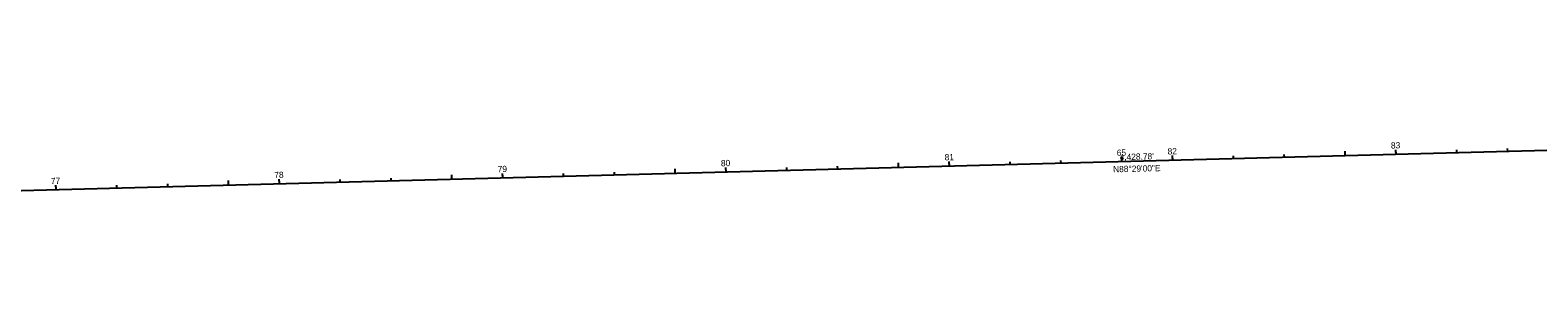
# Model space of a CAD drawing. Extents: x 2402033 to 2407434, y 498266 to 500417.
# Drawn here: x 2404722 to 2405397, y 498666 to 498783 of the extents above; entities that cross this region are included whole.
import ezdxf

# ---------------------------------------------------------------- set-up
doc = ezdxf.new("R2010")
doc.units = 0
for name, color, linetype in [('BR_P_Rail_Object', 7, 'Continuous'), ('DR_P_Inlet_Protection', 7, 'Continuous'), ('DR_X_Cells', 7, 'Continuous'), ('DR_X_Elev_Flow', 7, 'Continuous'), ('PV_P_EOP', 7, 'Continuous'), ('PV_P_Shoulder', 7, 'Continuous'), ('RD_P_GR_Lt', 7, 'Continuous'), ('SN_X_Public', 7, 'Continuous'), ('UT_X_Gas_Cells', 7, 'Continuous'), ('UT_X_Telecom_Cells', 7, 'Continuous')]:
    doc.layers.add(name, color=color, linetype=linetype)

msp = doc.modelspace()

# ---------------------------------------------------------------- linework, layer by layer
at = {"layer": 'PV_P_EOP'}
msp.add_line((2403004.47, 498665.82), (2407431.7, 498783.04), dxfattribs=at)
at = {"layer": 'PV_P_Shoulder'}
for p, q in [((2405210.95, 498724.24), (2405210.89, 498726.24)), ((2405233.69, 498724.84), (2405233.66, 498726.04)), ((2405310.91, 498726.89), (2405310.88, 498728.08)), ((2405333.66, 498727.49), (2405333.63, 498728.69)), ((2404911.05, 498716.3), (2404911.02, 498717.5)), ((2404933.8, 498716.9), (2404933.77, 498718.1)), ((2405011.02, 498718.95), (2405010.99, 498720.14)), ((2405033.76, 498719.55), (2405033.71, 498721.55)), ((2405110.98, 498721.59), (2405110.95, 498722.79)), ((2405133.73, 498722.19), (2405133.7, 498723.39)), ((2404733.87, 498711.61), (2404733.84, 498712.81)), ((2404811.09, 498713.65), (2404811.06, 498714.85)), ((2404833.83, 498714.25), (2404833.8, 498715.45))]:
    msp.add_line(p, q, dxfattribs=at)
at = {"layer": 'RD_P_GR_Lt'}
for p, q in [((2405133.73, 498722.19), (2405133.67, 498724.19)), ((2405160.96, 498722.92), (2405160.93, 498724.11)), ((2405183.71, 498723.52), (2405183.68, 498724.72)), ((2405210.95, 498724.24), (2405210.89, 498726.24)), ((2405233.69, 498724.84), (2405233.64, 498726.84)), ((2405260.93, 498725.56), (2405260.9, 498726.76)), ((2405283.67, 498726.16), (2405283.64, 498727.36)), ((2405310.91, 498726.89), (2405310.86, 498728.88)), ((2405333.66, 498727.49), (2405333.6, 498729.49)), ((2405360.89, 498728.21), (2405360.86, 498729.41)), ((2405383.64, 498728.81), (2405383.61, 498730.01)), ((2404911.05, 498716.3), (2404911, 498718.3)), ((2404933.8, 498716.9), (2404933.74, 498718.9)), ((2404961.03, 498717.62), (2404961, 498718.82)), ((2404983.78, 498718.22), (2404983.75, 498719.42)), ((2405011.02, 498718.95), (2405010.96, 498720.94)), ((2405033.76, 498719.55), (2405033.71, 498721.55)), ((2405061, 498720.27), (2405060.97, 498721.47)), ((2405083.74, 498720.87), (2405083.71, 498722.07)), ((2405110.98, 498721.59), (2405110.93, 498723.59)), ((2404733.87, 498711.61), (2404733.81, 498713.61)), ((2404761.1, 498712.33), (2404761.07, 498713.53)), ((2404783.85, 498712.93), (2404783.82, 498714.13)), ((2404811.09, 498713.65), (2404811.03, 498715.65)), ((2404833.83, 498714.25), (2404833.78, 498716.25)), ((2404861.07, 498714.98), (2404861.04, 498716.18)), ((2404883.81, 498715.58), (2404883.78, 498716.78))]:
    msp.add_line(p, q, dxfattribs=at)
at = {"layer": 'SN_X_Public'}
for p, q in [((2405210.95, 498724.24), (2405210.92, 498725.44)), ((2405033.76, 498719.55), (2405033.71, 498721.55))]:
    msp.add_line(p, q, dxfattribs=at)

# ---------------------------------------------------------------- texts
at = {"layer": 'BR_P_Rail_Object'}
msp.add_text('N88°29\'00"E', height=2.8, rotation=1.5166, dxfattribs=at).set_placement((2405207.04, 498719.33))
at = {"layer": 'DR_P_Inlet_Protection'}
msp.add_text('N88°29\'00"E', height=2.8, rotation=1.5166, dxfattribs=at).set_placement((2405207.04, 498719.33))
at = {"layer": 'DR_X_Cells'}
msp.add_text('N88°29\'00"E', height=2.8, rotation=1.5166, dxfattribs=at).set_placement((2405207.04, 498719.33))
at = {"layer": 'DR_X_Elev_Flow'}
msp.add_text("4,428.78'", height=2.8, rotation=1.5166, dxfattribs=at).set_placement((2405209.96, 498724.78))
at = {"layer": 'PV_P_Shoulder'}
for s, p in [('80', (2405031.5, 498722.04)), ('65', (2405208.69, 498726.72))]:
    msp.add_text(s, height=2.8, rotation=1.5166, dxfattribs=at).set_placement(p)
at = {"layer": 'RD_P_GR_Lt'}
for s, p in [('83', (2405331.41, 498729.98)), ('80', (2405031.5, 498722.04)), ('81', (2405131.64, 498724.69)), ('82', (2405231.44, 498727.33)), ('78', (2404831.57, 498716.74)), ('79', (2404931.57, 498719.39)), ('77', (2404731.55, 498714.05))]:
    msp.add_text(s, height=2.8, rotation=1.5166, dxfattribs=at).set_placement(p)
at = {"layer": 'SN_X_Public'}
msp.add_text('80', height=2.8, rotation=1.5166, dxfattribs=at).set_placement((2405031.5, 498722.04))
at = {"layer": 'UT_X_Gas_Cells'}
msp.add_text("4,428.78'", height=2.8, rotation=1.5166, dxfattribs=at).set_placement((2405209.96, 498724.78))
at = {"layer": 'UT_X_Telecom_Cells'}
msp.add_text("4,428.78'", height=2.8, rotation=1.5166, dxfattribs=at).set_placement((2405209.96, 498724.78))

doc.saveas('drawing.dxf')
